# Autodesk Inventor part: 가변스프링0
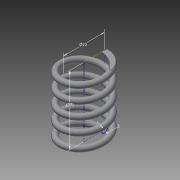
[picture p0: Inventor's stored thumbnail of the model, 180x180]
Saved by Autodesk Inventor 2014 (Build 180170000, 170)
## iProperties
Created: 2015-02
Part Number: 가변스프링0
Material: 일반
Document SubType Name: Modeling
Designer: basic
Density: 1 g/cm^3
Appearance: 기본값
Author: basic
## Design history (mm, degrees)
sketch "스케치1"
  geometry: L1 (0, 0)-(11, 0); L2 (11, 0)-(11, 37); L3 (11, 37)-(0, 37); L4 (0, 37)-(0, 0); C1 r 1.5 at (11, 0)
  constraints: 8 end point, 2 parallel, 1 centre point, 1 coincident, 1 horizontal, 1 perpendicular
  dimensions: "d0" = 22 diameter of L2 L4; "d1" = 37 distance of L3.end L1.start (derived); "d2" = 3 diameter of C1
feature "코일1" sketch "스케치1" pitch "d3" = 10; turns "d5" = 5; dims "d4" = 37 (= d1), "d6" = 0, angle "d7" = 90 deg, angle "d8" = 90 deg, "d9" = 0, "d10" = 0
sketch "스케치2"
  geometry: L1 (0, 12.5)-(0, 9.5) reference; L2 (0, 12.5)-(0, 9.5) reference; 1 further point
  constraints: 2 vertical alignment
extrude "돌출1" cut sketch "스케치2" stored distance "d11" = 10; taper "d12" = 0 deg
node "작업 평면1"
sketch "스케치3"
  geometry: L1 (1.5, 0)-(-1.5, 0) reference; 1 further point
  constraints: 1 horizontal alignment
extrude "돌출2" cut sketch "스케치3" stored distance "d14" = 10; taper "d15" = 0 deg
node "솔리드1"
node "절단 모서리 투영1"
node "절단 모서리 투영2"
node "절단 모서리 투영3"
other parameters: "d13" = 0
